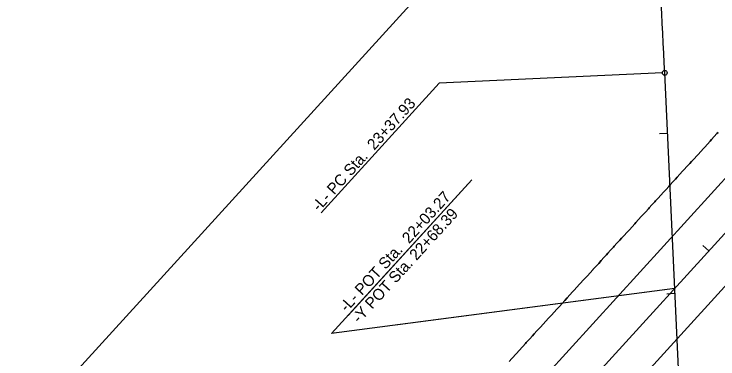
# Model space of a CAD drawing. Extents: x 1807040 to 1808827, y 913493 to 915218.
# Drawn here: x 1807478.3 to 1807917.6, y 914664.2 to 914879.4 of the extents above; entities that cross this region are included whole.
import ezdxf

# ---------------------------------------------------------------- set-up
doc = ezdxf.new("R2010")
doc.units = 0
for name, color, linetype in [('Prop EOT', 7, 'Continuous'), ('Prop Horizontal Alignment Station Label', 7, 'Continuous'), ('Prop Horizontal Alignment Tick Small', 7, 'Continuous'), ('Scratch_Level_0', 7, 'Continuous'), ('Scratch_Level_1', 7, 'Continuous'), ('Scratch_Level_3', 7, 'Continuous')]:
    doc.layers.add(name, color=color, linetype=linetype)

msp = doc.modelspace()

# ---------------------------------------------------------------- linework, layer by layer
at = {"layer": 'Prop EOT'}
for p, q in [((1807702.96, 914536.44), (1808029.68, 914894.91)), ((1807613.95, 914371.74), (1808063.17, 914864.38))]:
    msp.add_line(p, q, dxfattribs=at)
msp.add_lwpolyline([(1807787.37, 914662.72), (1807789.06, 914664.57), (1807789.61, 914665.17), (1807791.29, 914667.02), (1807791.83, 914667.63), (1807793.54, 914669.46), (1807793.82, 914669.77), (1807795.5, 914671.62), (1807795.76, 914671.91), (1807797.44, 914673.77), (1807797.99, 914674.39), (1807799.68, 914676.24), (1807800.21, 914676.82), (1807801.9, 914678.67), (1807802.94, 914679.81), (1807804.62, 914681.67), (1807805.2, 914682.31), (1807806.89, 914684.15), (1807808.57, 914685.99), (1807810.26, 914687.84), (1807811.95, 914689.68), (1807813.64, 914691.52), (1807815.33, 914693.37), (1807817.02, 914695.21), (1807818.71, 914697.05), (1807820.39, 914698.9), (1807822.08, 914700.74), (1807823.51, 914702.3), (1807825.18, 914704.16), (1807826.86, 914706.02), (1807827.91, 914707.18), (1807829.6, 914709.03), (1807831.29, 914710.87), (1807831.9, 914711.53), (1807833.59, 914713.37), (1807835.28, 914715.21), (1807836.13, 914716.14), (1807837.81, 914717.99), (1807839.5, 914719.83), (1807839.8, 914720.17), (1807841.49, 914722.01), (1807843.18, 914723.86), (1807844.76, 914725.58), (1807846.45, 914727.43), (1807848.14, 914729.27), (1807848.98, 914730.19), (1807850.66, 914732.04), (1807852.35, 914733.88), (1807852.95, 914734.55), (1807854.62, 914736.41), (1807856.3, 914738.27), (1807857.39, 914739.49), (1807859.09, 914741.33), (1807860.78, 914743.17), (1807862.33, 914744.86), (1807864.01, 914746.71), (1807865.69, 914748.56), (1807866.41, 914749.35), (1807868.1, 914751.19), (1807869.79, 914753.04), (1807870.85, 914754.2), (1807872.53, 914756.04), (1807874.22, 914757.89), (1807874.79, 914758.51), (1807876.46, 914760.36), (1807878.14, 914762.22), (1807878.66, 914762.8), (1807880.35, 914764.64), (1807882.04, 914766.49), (1807883.6, 914768.2), (1807885.28, 914770.05), (1807886.97, 914771.9), (1807887.78, 914772.79), (1807889.47, 914774.64), (1807891.16, 914776.48), (1807892.21, 914777.62), (1807893.89, 914779.47), (1807895.58, 914781.32), (1807896.63, 914782.48), (1807898.31, 914784.32), (1807900, 914786.17), (1807901.06, 914787.34), (1807902.74, 914789.18), (1807904.43, 914791.02), (1807905.21, 914791.88), (1807906.9, 914793.73), (1807908.58, 914795.57), (1807909.39, 914796.46), (1807911.08, 914798.3), (1807912.77, 914800.15), (1807913.66, 914801.12), (1807915.34, 914802.97), (1807917.03, 914804.81), (1807917.73, 914805.58)], dxfattribs=at)
at = {"layer": 'Prop Horizontal Alignment Station Label'}
for p, q in [((1807882.93, 914842.68), (1807743.57, 914836.22)), ((1807669.88, 914755.37), (1807743.57, 914836.22)), ((1807676.5, 914680.01), (1807763.91, 914775.92)), ((1807686.91, 914691.44), (1807763.91, 914775.92)), ((1807890.66, 914708.24), (1807676.5, 914680.01)), ((1807890.66, 914708.24), (1807717.73, 914685.45))]:
    msp.add_line(p, q, dxfattribs=at)
msp.add_circle((1807884.43, 914842.75), 1.5, dxfattribs=at)
at = {"layer": 'Prop Horizontal Alignment Tick Small'}
for p, q in [((1807886.18, 914804.86), (1807881.19, 914804.63)), ((1807911.95, 914731.6), (1807908.26, 914734.97)), ((1807890.81, 914704.97), (1807885.82, 914704.73))]:
    msp.add_line(p, q, dxfattribs=at)
at = {"layer": 'Scratch_Level_0'}
for p, q in [((1807702.96, 914536.44), (1808029.68, 914894.91)), ((1808063.17, 914864.38), (1807658.9, 914421.03))]:
    msp.add_line(p, q, dxfattribs=at)
msp.add_lwpolyline([(1807917.73, 914805.58), (1807917.03, 914804.81), (1807915.34, 914802.97), (1807913.66, 914801.12), (1807912.77, 914800.15), (1807911.08, 914798.3), (1807909.39, 914796.46), (1807908.58, 914795.57), (1807906.9, 914793.73), (1807905.21, 914791.88), (1807904.43, 914791.02), (1807902.74, 914789.18), (1807901.06, 914787.34), (1807900, 914786.17), (1807898.31, 914784.32), (1807896.63, 914782.48), (1807895.58, 914781.32), (1807893.89, 914779.47), (1807892.21, 914777.62), (1807891.16, 914776.48), (1807889.47, 914774.64), (1807887.78, 914772.79), (1807886.97, 914771.9), (1807885.28, 914770.05), (1807883.6, 914768.2), (1807882.04, 914766.49), (1807880.35, 914764.64), (1807878.66, 914762.8), (1807878.14, 914762.22), (1807876.46, 914760.36), (1807874.79, 914758.51), (1807874.22, 914757.89), (1807872.53, 914756.04), (1807870.85, 914754.2), (1807869.79, 914753.04), (1807868.1, 914751.19), (1807866.41, 914749.35), (1807865.69, 914748.56), (1807864.01, 914746.71), (1807862.33, 914744.86), (1807860.78, 914743.17), (1807859.09, 914741.33), (1807857.39, 914739.49), (1807856.3, 914738.27), (1807854.62, 914736.41), (1807852.95, 914734.55), (1807852.35, 914733.88), (1807850.66, 914732.04), (1807848.98, 914730.19), (1807848.14, 914729.27), (1807846.45, 914727.43), (1807844.76, 914725.58), (1807843.18, 914723.86), (1807841.49, 914722.01), (1807839.8, 914720.17), (1807839.5, 914719.83), (1807837.81, 914717.99), (1807836.13, 914716.14), (1807835.28, 914715.21), (1807833.59, 914713.37), (1807831.9, 914711.53), (1807831.29, 914710.87), (1807829.6, 914709.03), (1807827.91, 914707.18), (1807826.86, 914706.02), (1807825.18, 914704.16), (1807823.51, 914702.3), (1807822.08, 914700.74), (1807820.39, 914698.9), (1807818.71, 914697.05), (1807817.02, 914695.21), (1807815.33, 914693.37), (1807813.64, 914691.52), (1807811.95, 914689.68), (1807810.26, 914687.84), (1807808.57, 914685.99), (1807806.89, 914684.15), (1807805.2, 914682.31), (1807804.62, 914681.67), (1807802.94, 914679.81), (1807801.9, 914678.67), (1807800.21, 914676.82), (1807799.68, 914676.24), (1807797.99, 914674.39), (1807797.44, 914673.77), (1807795.76, 914671.91), (1807795.5, 914671.62), (1807793.82, 914669.77), (1807793.54, 914669.46), (1807791.83, 914667.63), (1807791.29, 914667.02), (1807789.61, 914665.17), (1807789.06, 914664.57), (1807787.37, 914662.72)], dxfattribs=at)
at = {"layer": 'Scratch_Level_1'}
msp.add_lwpolyline([(1807040.33, 914133.66), (1807040.33, 914133.66), (1807428.35, 913780.01), (1808256.27, 914688.39), (1807868.25, 915042.04)], close=True, dxfattribs=at)
at = {"layer": 'Scratch_Level_3'}
for p, q in [((1807238.34, 913992.52), (1808046.68, 914879.41)), ((1807901, 914485.11), (1807884.43, 914842.75))]:
    msp.add_line(p, q, dxfattribs=at)
msp.add_arc((1803888.72, 914657.58), 4000, 2.65322, 5.4874, dxfattribs=at)

# ---------------------------------------------------------------- texts
at = {"layer": 'Prop Horizontal Alignment Station Label'}
for s, rotation, p in [('-L- PC Sta.  23+37.93', 47.9528, (1807668.64, 914755.85)), ('-L- POT Sta.  22+03.27', 47.6532, (1807685.97, 914693.12)), ('-L- POT Sta.  22+03.27', 47.6532, (1807685.97, 914693.12)), ('-Y POT Sta. 22+68.39', 47.6532, (1807693.73, 914686.05)), ('-Y POT Sta. 22+68.39', 47.6532, (1807693.73, 914686.05))]:
    msp.add_text(s, height=7, rotation=rotation, dxfattribs=at).set_placement(p)

doc.saveas('drawing.dxf')
